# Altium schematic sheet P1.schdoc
size 297 x 209 mm; Symbol: Drawing-Symbol_A4; @Project Name: arcade_Read; @Page Count: 1; @Update Date: 2026-05-24; @Create Date: 2026-05-24; @Schematic Name: Schematic1; @Page No: 1; @Page Name: P1; Company: EasyEDA.com; Version: V1.0; Page Size: A4; @Create Time: 19:48:25; @Update Time: 20:57:43; Border: 1; Width: 1170; Height: 825; Region Start: 1; X Region Count: 6; Y Region Count: 4; Blade Width: 10; Title Block Position: 3; @Board Name: Board1; Device: Drawing-Symbol_A4
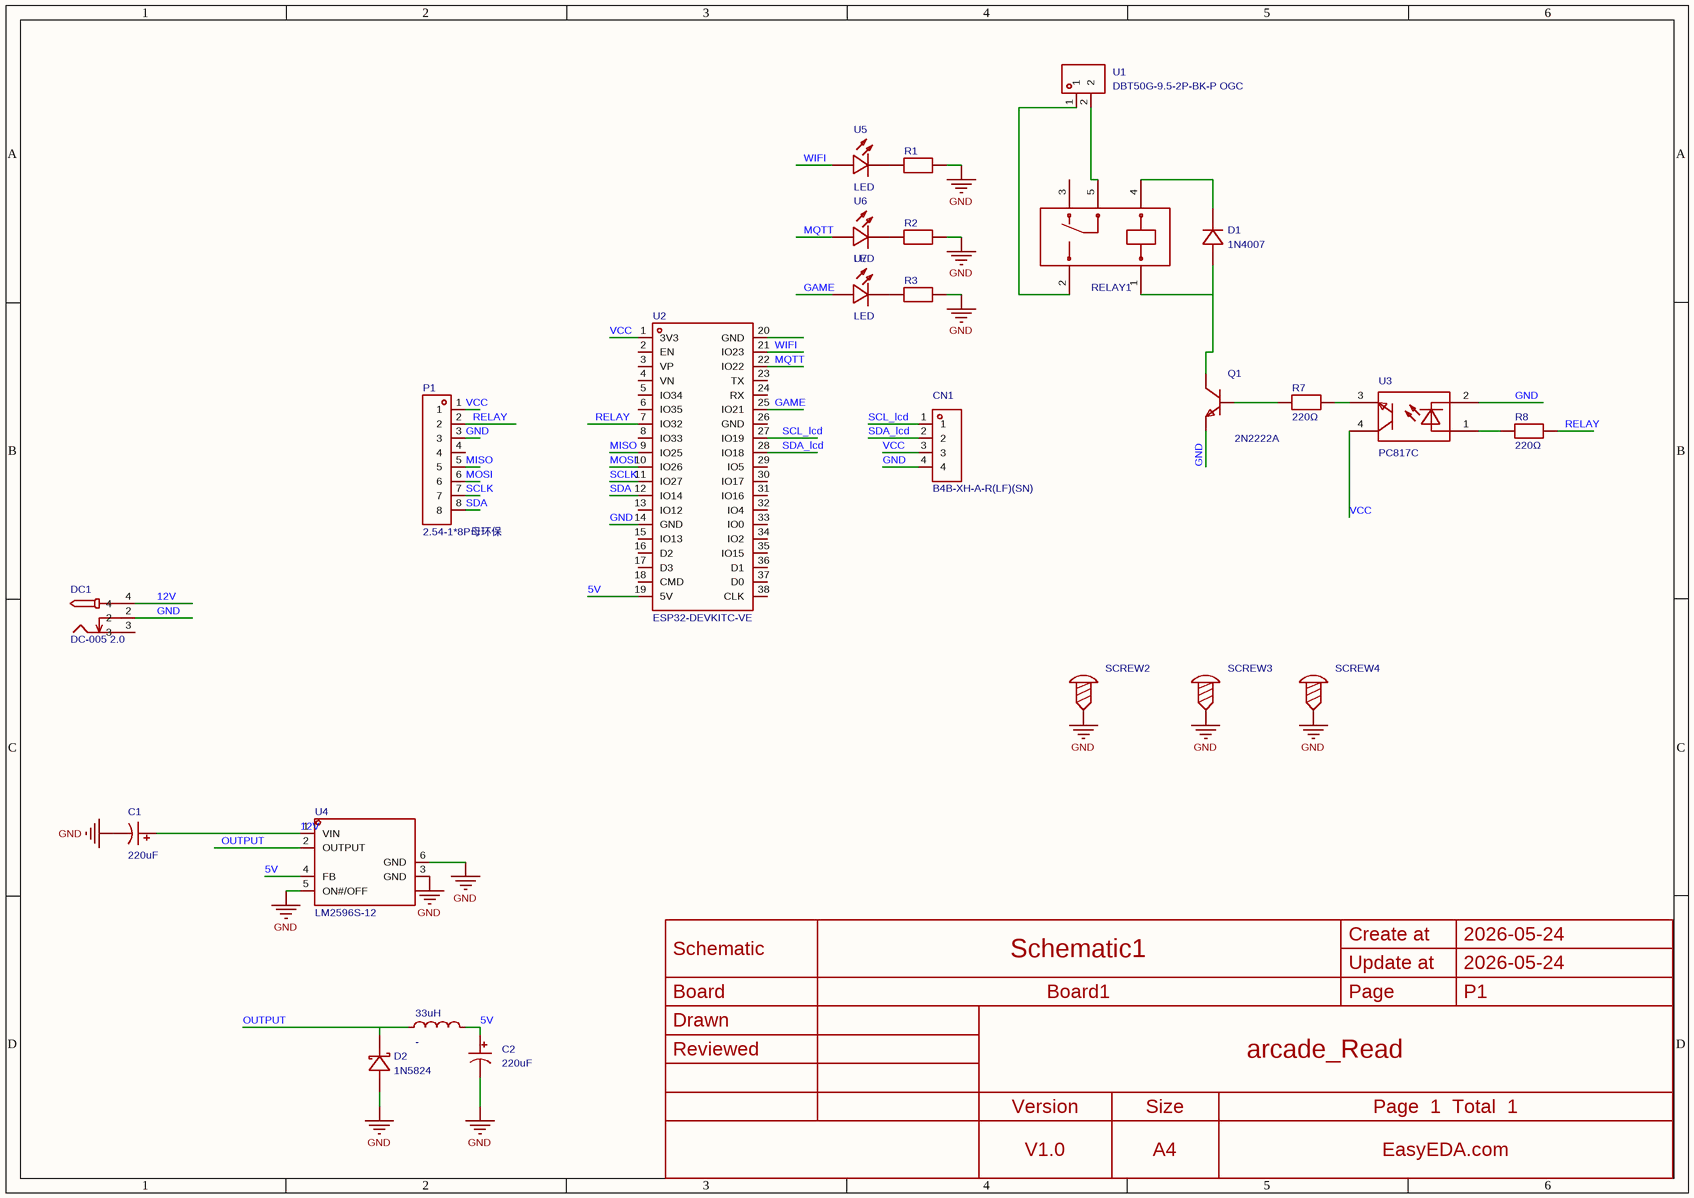
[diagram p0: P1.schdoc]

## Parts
33uH  -  [IND-TH_BD10.0-P5.00-D0.7]
C1  220uF  [CAP-TH_BD8.0-P3.50-D0.6-FD]
C2  220uF  [CAP-TH_BD8.0-P3.50-D0.6-FD]
CN1  B4B-XH-A-R(LF)(SN)  [CONN-TH_4P-P2.50_JST_B4B-XH-A-M]
D1  1N4007  [DO-41_BD2.4-L4.7-P8.70-D0.6-RD]
D2  1N5824  [DO-201AD_BD5.3-L9.0-P13.00-D1.3-RD]
DC1  DC-005 2.0  [DC-IN-TH_DC-005-5.5-2.0]
P1  2.54-1*8P母环保  [HDR-TH_8P-P2.54-V-F]
Q1  2N2222A  [TO-92-3_L5.1-W4.1-P1.27-L-1]
R1  AXIAL0.5 1K/0.5W/1%  [RES-TH_BD3.0-L9.0-P13.0-D0.6]  (value not drawn)
R2  AXIAL0.5 1K/0.5W/1%  [RES-TH_BD3.0-L9.0-P13.0-D0.6]  (value not drawn)
R3  AXIAL0.5 1K/0.5W/1%  [RES-TH_BD3.0-L9.0-P13.0-D0.6]  (value not drawn)
R7  220Ω  [RES-TH_BD3.5-P4.00-D0.7]
R8  220Ω  [RES-TH_BD3.5-P4.00-D0.7]
RELAY1  (no value)  [RELAY-TH_SRD-XXVDC-XL-C]
SCREW2  (no value)  [Screw-Hole-M3]
SCREW3  (no value)  [Screw-Hole-M3]
SCREW4  (no value)  [Screw-Hole-M3]
U1  DBT50G-9.5-2P-BK-P OGC  [CONN-TH_2P-P9.50_DBT50G-9.5-2P]
U2  ESP32-DEVKITC-VE  [BULETM-SMD_ESP32-DEVKITC]
U3  PC817C  [DIP-4_L6.5-W4.6-P2.54-LS7.6-BL]
U4  LM2596S-12  [TO-263-5_L10.1-W8.7-P1.70-LS14.4-BR]
U5  LED  [LED-TH_BD4.0-P2.54-FD_RED]
U6  LED  [LED-TH_BD4.0-P2.54-FD_RED]
U7  LED  [LED-TH_BD4.0-P2.54-FD_RED]

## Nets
GND: C1.2 C2.2 CN1.4 D2.2(A) DC1.2 P1.3 Q1.1(E) R1.2 R2.2 R3.2 SCREW2.1 SCREW3.1 SCREW4.1 U2.14(GND) U3.2 U4.3(GND) U4.5(ON#/OFF) U4.6(GND)
5V: 33uH.2 C2.1 U2.19(5V) U4.4(FB)
12V: C1.1 DC1.4 U4.1(VIN)
GAME: U2.25(IO21) U7.1(+)
MISO: P1.5 U2.9(IO25)
MOSI: P1.6 U2.10(IO26)
MQTT: U2.22(IO22) U6.1(+)
OUTPUT: 33uH.1 D2.1(K) U4.2(OUTPUT)
RELAY: P1.2 R8.2 U2.7(IO32)
SCL_lcd: CN1.1 U2.27(IO19)
SCLK: P1.7 U2.11(IO27)
SDA: P1.8 U2.12(IO14)
SDA_lcd: CN1.2 U2.28(IO18)
VCC: CN1.3 P1.1 U2.1(3V3) U3.4
WIFI: U2.21(IO23) U5.1(+)
NetD1_1: D1.1(K) RELAY1.4
NetD1_2: D1.2(A) Q1.3(C) RELAY1.1
NetQ1_2: Q1.2(B) R7.1
NetR1_1: R1.1 U5.2(-)
NetR2_1: R2.1 U6.2(-)
NetR3_1: R3.1 U7.2(-)
NetR7_2: R7.2 U3.3
NetR8_1: R8.1 U3.1
NetRELAY1_2: RELAY1.2 U1.1
NetRELAY1_5: RELAY1.5 U1.2

Not connected (* = marked no-connect by the designer): DC1 3; P1 4; RELAY1 3; U2 2(EN) 3(VP) 4(VN) 5(IO34) 6(IO35) 8(IO33) 13(IO12) 15(IO13) 16(D2) 17(D3) 18(CMD) 20(GND) 23(TX) 24(RX) 26(GND) 29(IO5) 30(IO17) 31(IO16) 32(IO4) 33(IO0) 34(IO2) 35(IO15) 36(D1) 37(D0) 38(CLK)

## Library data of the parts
33uH = SH0810.220K: Inductance:- Current Rating:- Current - Saturation(Isat):2.4A DC Resistance(DCR):47mΩ Ratings:-; Manufacturer: SOREDE(索瑞达); AddInBom: yes; ModelId: 6f9ee062f7de4d6590fce85b5ec5ebc30819f05c4eef4c71ace90d822a990e87; ModelName: IND-TH_D10.0-P5.0; ModelTransform: 354.09508,354.21252,0,0,0,0,-0.079,0,-129.921; Current - Saturation(Isat): 2.4A; DC Resistance(DCR): 47mΩ
C1 C2 = ERS1VM221F12OT: Capacitance:220uF Tolerance:±20% Tolerance:±20% Voltage Rating:35V Pin Spacing:3.5mm Diameter:8mm Height - Seated (Max):12mm Lifetime:7000hrs@105℃; Manufacturer: AISHI(艾华集团); AddInBom: yes; ModelId: 26f37486632942dc87f6308ee91e8f400819f05c4eef4c71ace90d822a990e87; ModelName: CAP-TH_D8.0-H8.0-P3.50; ModelTransform: 314.96,314.862,0,180,0,0,0,0,-137.795; Tolerance: ±20%; Voltage Rating: 35V; Pin Spacing: 3.5mm
CN1 = B4B-XH-A-R(LF)(SN): Pins Structure:1x4P Pitch:2.5mm Mounting Style:Direct Insert Reference Series:XH Number of Pins:4P Number of Rows:1 Number of PINs Per Row:4 Row Spacing:- Current Rating (Max):3A Contact Material:Brass Contact Plating:Tin Operating Temperature Range:-25℃~; Manufacturer: JST; AddInBom: yes; ModelId: 0d75b1ca4e4a401e85f7c090d37293500819f05c4eef4c71ace90d822a990e87; ModelTransform: 488.5817,226.378,0,0,0,0,-0.002,21.654,-137.795; Pins Structure: 1x4P; Pitch: 2.5mm; Reference Series: XH; Number of PINs Per Row: 4; Current Rating (Max): 3A; Rated Voltage (Max): 250V; Plastic Material: PA66; Flame Retardant Rating: UL94V-0; Supplementary Features: K-leg punch; Z-Height of the Board: 7mm; X-Length of Bottom Edge on Board (Spacing Line): 12.4mm; Y-Width of Bottom Edge on Board: 5.75mm
D1 = 1N4007_C53058793: Manufacturer: luJing(鲁晶); AddInBom: yes; ModelId: 39d8e4572d564e62a86d2224fc908dd8; ModelName: DO-41_D2.4-L4.7-P8.70; ModelTransform: 374.015,94.428,0,0,0,0,0,0,-137.795
D2 = 1N5824_C27636124: Manufacturer: DOWO(东沃); AddInBom: yes; ModelId: b3fd1a8e56f64f849760764501a18ba60819f05c4eef4c71ace90d822a990e87; ModelTransform: 562.991,209.02013,0,0,0,0,0,0,-196.85
DC1 = DC-005 2.0: Connector Type:DC Power Jack Mounting Type:Right Angle Inside Contact Diameter:2mm Outside Contact Diameter:6.4mm Current Rating:1A Voltage Rating (Max):12V Operating Temperature:-25℃~+85℃ Operating Temperature:-25℃~+85℃; Manufacturer: BOOMELE(博穆精密); Symbol: DC-005 5.5-2.0MM; AddInBom: yes; ModelId: 4f53e78914cc40d981a5164b319825df0819f05c4eef4c71ace90d822a990e87; ModelName: DC-IN-TH_DC-5520-1; ModelTransform: 372.0465,551.18,0,270,0,0,-143.701,80.709,-149.606; Inside Contact Diameter: 2mm; Outside Contact Diameter: 6.4mm; Current Rating: 1A; Voltage Rating (Max): 12V
P1 = 2.54-1*8P母环保: Holes Structure:1x8P Pitch:2.54mm Row Spacing:- Circular Hole / Square Hole:Square Hole Mounting Type:Through Hole Number of Rows:1 Number of Positions:8P Current Rating:3A Holes Direction:Top Insulation Height:8.5mm Contact Material:Brass Contact Plating; Manufacturer: BOOMELE(博穆精密); Symbol: Header-Female-2.54_1x8; AddInBom: yes; ModelId: 6ab1dac21d924c3d8eea0dfa46d42ff5; ModelTransform: 819.723,98.425,0,0,0,0,0,0,-118.11; Holes Structure: 1x8P; Pitch: 2.54mm; Number of Positions: 8P; Current Rating: 3A; Holes Direction: Top; PIN Length: 3.2mm
Q1 = 2N2222A_C50229645: Manufacturer: DDF(鼎德丰); AddInBom: yes; ModelId: 756aef4d00494ec0b207813f8150ad3d; ModelTransform: 200.42283,161.417,0,0,0,0,0,9.842,-196.85
R1-R3 = AXIAL0.5 1K/0.5W/1%: AddInBom: yes; ModelId: b5dd1184829b45df9f0f2ff6764257690819f05c4eef4c71ace90d822a990e87; ModelTransform: 535.432,118.11,0,0,0,0,0,0,-196.85
R7 R8 = RSS1W0R1JPA: Type:Metal Oxide Film Resistor Resistance:100mΩ Tolerance:±5% Tolerance:±5% Power(Watts):1W Temperature Coefficient:±300ppm/℃ Temperature Coefficient:±300ppm/℃ Operating Temperature:-55℃~+155℃ Operating Temperature:-55℃~+155℃; Manufacturer: Tyohm(幸亚电阻); AddInBom: yes; Tolerance: ±5%; Power(Watts): 1W
RELAY1 = SRD-12VDC-SL-C: Coil Voltage:12V Contact Form:1 Form C: 1C (SPDT-CO) Number of Pins:5 Contact Rating:- Switching Voltage(Max):250V@AC Coil Rated Power:360mW Switching Current(Max):15A Coil Type:Non-Polarized - Single Coil Coil Resistance:400Ω Contact Resistance:100mΩ Ope; Manufacturer: 松乐; AddInBom: yes; ModelId: 1a3dde03f09f4597ad61ffbe4563483d; ModelName: RELAY-TH_L19.2-W15.6-H15.8; ModelTransform: 755.904,622.4397,0,0,0,0,34.882,0,-118.11; Coil Voltage: 12V; Coil Rated Power: 360mW; Switching Current(Max): 15A; Coil Resistance: 400Ω; Contact Resistance: 100mΩ; Operate Time: 10ms
SCREW2-SCREW4 = Screw-Hole-M3: ConvertToPcb: yes
U1 = DBT50G-9.5-2P-BK-P OGC: Barrier Type:With Cover Plate Pitch:9.5mm Number of Positions or Pins:1x2P Mounting Type:Straight Pin Location:Side Mount Number of Pins:2P Number of Rows:1 Number of PINs Per Row:2 Screw Specification:- Current Rating:- Voltage Rating (Max):- Wire Gauge; Manufacturer: DORABO(地博电气); AddInBom: yes; ModelId: 3e736245c38341d9911e1e2418f3a9620819f05c4eef4c71ace90d822a990e87; ModelTransform: 807.08894,637.79361,0,0,0,0,0,-149.606,-141.732; Pitch: 9.5mm; Number of Positions or Pins: 1x2P; Number of PINs Per Row: 2; Wire Gauge - AWG: 12~22; Wire Gauge - mm2: 4
U2 = ESP32-DEVKITC-VE: Manufacturer: ESPRESSIF(乐鑫); AddInBom: yes
U3 = PC817C_C52098316: Features:-; Manufacturer: YONGYUTAI(永裕泰); AddInBom: yes; ModelId: 5dd07e8c09c24613b5f0b95cb6423302; ModelName: DIP-4_L6.5-W4.6-H3.5-LS7.62-P2.54; ModelTransform: 180.3146,311.8104,0,0,0,0,0.004,-0.002,-137.795
U4 = LM2596S-12_C42421957: Function:Step-down type Voltage - Supply:40V Voltage - Supply:40V Output Voltage:12V Output Voltage:12V Output Current:3A Frequency - Switching:150kHz Frequency - Switching:150kHz Operating Temperature:-40℃~+125℃ Operating Temperature:-40℃~+125℃ Synchrono; Manufacturer: TDSEMIC(拓电半导体); AddInBom: yes; ModelId: 47038617168443b392e2b8a12674fa180819f05c4eef4c71ace90d822a990e87; ModelName: TO-263-5_L10.13-W8.74-P1.70-LS14.38-BR; ModelTransform: 405.511,562.20364,0,90,0,0,-52.721,0.002,0; Voltage - Supply: 40V; Output Voltage: 12V; Output Current: 3A; Frequency - Switching: 150kHz; Synchronous Rectifier: No; Number of Outputs: 1; Topology: Buck; Quiescent Current: 5mA; Switch tube (built-in/external): Built-in; Output Type: Fixed
U5-U7 = LED: Symbol: LED_C9900015665; AddInBom: yes; ModelId: ebc6af6b0c6f45ef98776efe17486e550819f05c4eef4c71ace90d822a990e87; ModelTransform: 137.561,157.46465,0,0,0,0,-8.858,0,-196.85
